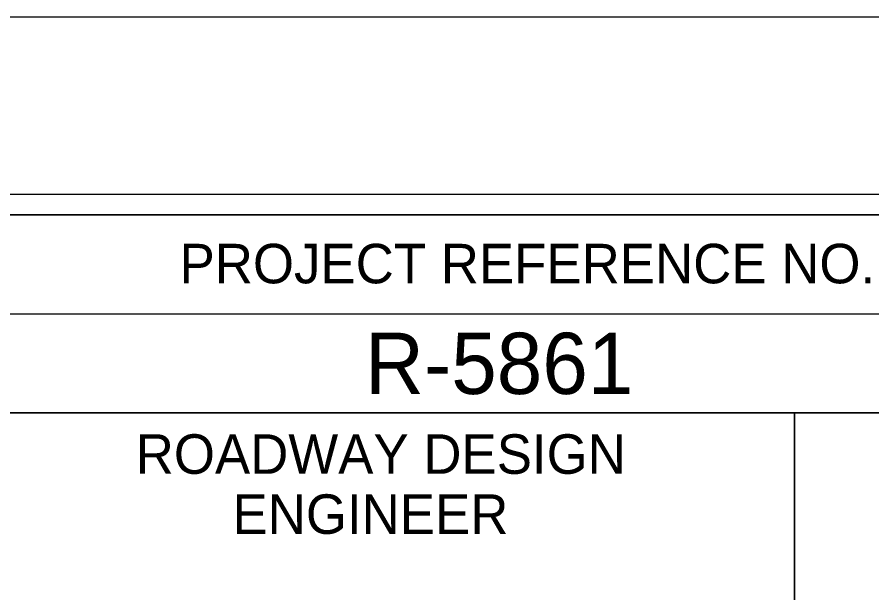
# Model space of a CAD drawing. Extents: x 497599 to 513368, y 404140 to 476034.
# Drawn here: x 507160.3 to 507268.5, y 439788.3 to 439861.1 of the extents above; entities that cross this region are included whole.
import ezdxf

# ---------------------------------------------------------------- set-up
doc = ezdxf.new("R2010")
doc.units = 0
for name, color, linetype in [('Sheet Cutting Line CELL', 7, 'Continuous'), ('Sheet Data Field CELL', 7, 'Continuous'), ('Sheet Layout Profile Border Port 2', 7, 'Continuous'), ('Sheet Plot Border Inside CELL', 7, 'Continuous'), ('Sheet Plot Border Outside CELL', 7, 'Continuous'), ('Sheet Profile CELL', 7, 'Continuous'), ('Sheet Profile Grid Major CELL', 7, 'Continuous'), ('Sheet Profile Grid Minor CELL', 7, 'Continuous')]:
    doc.layers.add(name, color=color, linetype=linetype)

msp = doc.modelspace()

# ---------------------------------------------------------------- linework, layer by layer
at = {"layer": 'Sheet Cutting Line CELL'}
msp.add_line((507375.68, 439861.14), (505691.68, 439861.14), dxfattribs=at)
at = {"layer": 'Sheet Layout Profile Border Port 2'}
msp.add_lwpolyline([(505908.68, 439836.14), (507308.68, 439836.14), (507308.68, 439336.14), (505908.68, 439336.14)], close=True, dxfattribs=at)
at = {"layer": 'Sheet Plot Border Inside CELL'}
msp.add_lwpolyline([(505704.68, 438783.59), (507371.18, 438783.59), (507371.18, 439838.69), (505704.68, 439838.69)], close=True, dxfattribs=at)
at = {"layer": 'Sheet Plot Border Outside CELL'}
msp.add_lwpolyline([(505691.68, 438761.14), (507375.68, 438761.14), (507375.68, 439861.14), (505691.68, 439861.14)], close=True, dxfattribs=at)
at = {"layer": 'Sheet Profile CELL'}
for p, q in [((507158.63, 439823.59), (507358.68, 439823.59)), ((507258.68, 439811.09), (507258.68, 439698.64))]:
    msp.add_line(p, q, dxfattribs=at)
for points in [[(507358.68, 439836.14), (505858.68, 439836.14), (505858.68, 438786.14), (507358.68, 438786.14)], [(507158.63, 439836.14), (507358.68, 439836.14), (507358.68, 439811.09), (507158.63, 439811.09)], [(507158.63, 439811.09), (507258.68, 439811.09), (507258.68, 439698.59), (507158.63, 439698.59)], [(507258.68, 439811.09), (507358.68, 439811.09), (507358.68, 439698.59), (507258.68, 439698.59)]]:
    msp.add_lwpolyline(points, close=True, dxfattribs=at)
at = {"layer": 'Sheet Profile Grid Major CELL'}
msp.add_lwpolyline([(506708.68, 439336.14), (506758.68, 439336.14), (506758.68, 439836.14), (506808.68, 439836.14), (506808.68, 439336.14), (506858.68, 439336.14), (506858.68, 439836.14), (506908.68, 439836.14), (506908.68, 439336.14), (506958.68, 439336.14), (506958.68, 439836.14), (507008.68, 439836.14), (507008.68, 439336.14), (507058.68, 439336.14), (507058.68, 439836.14), (507108.68, 439836.14), (507108.68, 439336.14), (507158.68, 439336.14), (507158.68, 439836.14), (507184.98, 439836.14)], dxfattribs=at)
at = {"layer": 'Sheet Profile Grid Minor CELL'}
msp.add_lwpolyline([(507153.68, 439836.14), (507163.68, 439836.14)], dxfattribs=at)

# ---------------------------------------------------------------- texts
at = {"layer": 'Sheet Data Field CELL'}
msp.add_text('R-5861', height=7.75, dxfattribs=at).set_placement((507204.29, 439813.46))
at = {"layer": 'Sheet Profile CELL'}
for s, height, p in [('PROJECT REFERENCE NO.', 5.0001, (507180.84, 439827.46)), ('ROADWAY DESIGN', 5.0001, (507175.29, 439803.36)), ('ENGINEER', 5, (507187.54, 439795.76))]:
    msp.add_text(s, height=height, dxfattribs=at).set_placement(p)

doc.saveas('drawing.dxf')
